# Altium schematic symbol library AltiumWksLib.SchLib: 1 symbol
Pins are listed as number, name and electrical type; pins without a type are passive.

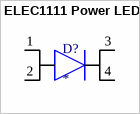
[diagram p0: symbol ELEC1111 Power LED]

## ELEC1111 Power LED
designator D?
An LED used in ELEC1111
footprint Model Name (Footprint not found)
footprint ELEC1111_PowerLED
pins: 1, 2, 3, 4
